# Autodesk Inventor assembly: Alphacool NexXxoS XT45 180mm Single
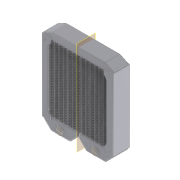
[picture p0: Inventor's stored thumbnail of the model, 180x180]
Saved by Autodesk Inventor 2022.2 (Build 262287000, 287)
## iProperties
Created: 2016-11
Part Number: Alphacool NexXxoS XT45 180mm Single
Document SubType Name: Assembly
Designer: 18907419
Author: 18907419
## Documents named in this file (6)
- C:\Users\18907419\Desktop\frigo\Alphacool NexXxoS XT45 180mm Single.iam
- C:\Users\18907419\Desktop\frigo\Copie de Alphacool NexXxoS XT45 180mm Single^Alphacool NexXxoS XT45 180mm Single.ipt
- C:\Users\18907419\Desktop\frigo\Copie de Jupe^Alphacool NexXxoS XT45 180mm Single.ipt
- C:\Users\18907419\Desktop\frigo\Copie de Ailette v2^Alphacool NexXxoS XT45 180mm Single.ipt
- C:\Users\18907419\Desktop\frigo\Bouchon.ipt
- C:\Users\18907419\Desktop\frigo\Bitspower_G14-1-2.ipt
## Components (21 placed, 5 different names)
1. Copie de Alphacool NexXxoS XT45 180mm Single^Alphacool NexXxoS XT45 180mm Single:1 — Simmetria:1
2. Copie de Jupe^Alphacool NexXxoS XT45 180mm Single:1 — Simmetria:1
3. Copie de Ailette v2^Alphacool NexXxoS XT45 180mm Single:1
4. Copie de Ailette v2^Alphacool NexXxoS XT45 180mm Single:2
5. Copie de Ailette v2^Alphacool NexXxoS XT45 180mm Single:3
6. Copie de Ailette v2^Alphacool NexXxoS XT45 180mm Single:4
7. Copie de Ailette v2^Alphacool NexXxoS XT45 180mm Single:5
8. Copie de Ailette v2^Alphacool NexXxoS XT45 180mm Single:6
9. Copie de Ailette v2^Alphacool NexXxoS XT45 180mm Single:7
10. Copie de Ailette v2^Alphacool NexXxoS XT45 180mm Single:8
11. Copie de Ailette v2^Alphacool NexXxoS XT45 180mm Single:9
12. Copie de Ailette v2^Alphacool NexXxoS XT45 180mm Single:10
13. Copie de Ailette v2^Alphacool NexXxoS XT45 180mm Single:11
14. Copie de Ailette v2^Alphacool NexXxoS XT45 180mm Single:12
15. Copie de Ailette v2^Alphacool NexXxoS XT45 180mm Single:13
16. Copie de Ailette v2^Alphacool NexXxoS XT45 180mm Single:14
17. Copie de Ailette v2^Alphacool NexXxoS XT45 180mm Single:15
18. Bouchon:1
19. Bitspower_G14-1-2:1
20. Bitspower_G14-1-2:2
21. Bouchon:2
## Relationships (1: Symmetry 1)
- Simmetria:1 [Symmetry]: Copie de Alphacool NexXxoS XT45 180mm Single^Alphacool NexXxoS XT45 180mm Single:1 ↔ Copie de Jupe^Alphacool NexXxoS XT45 180mm Single:1
